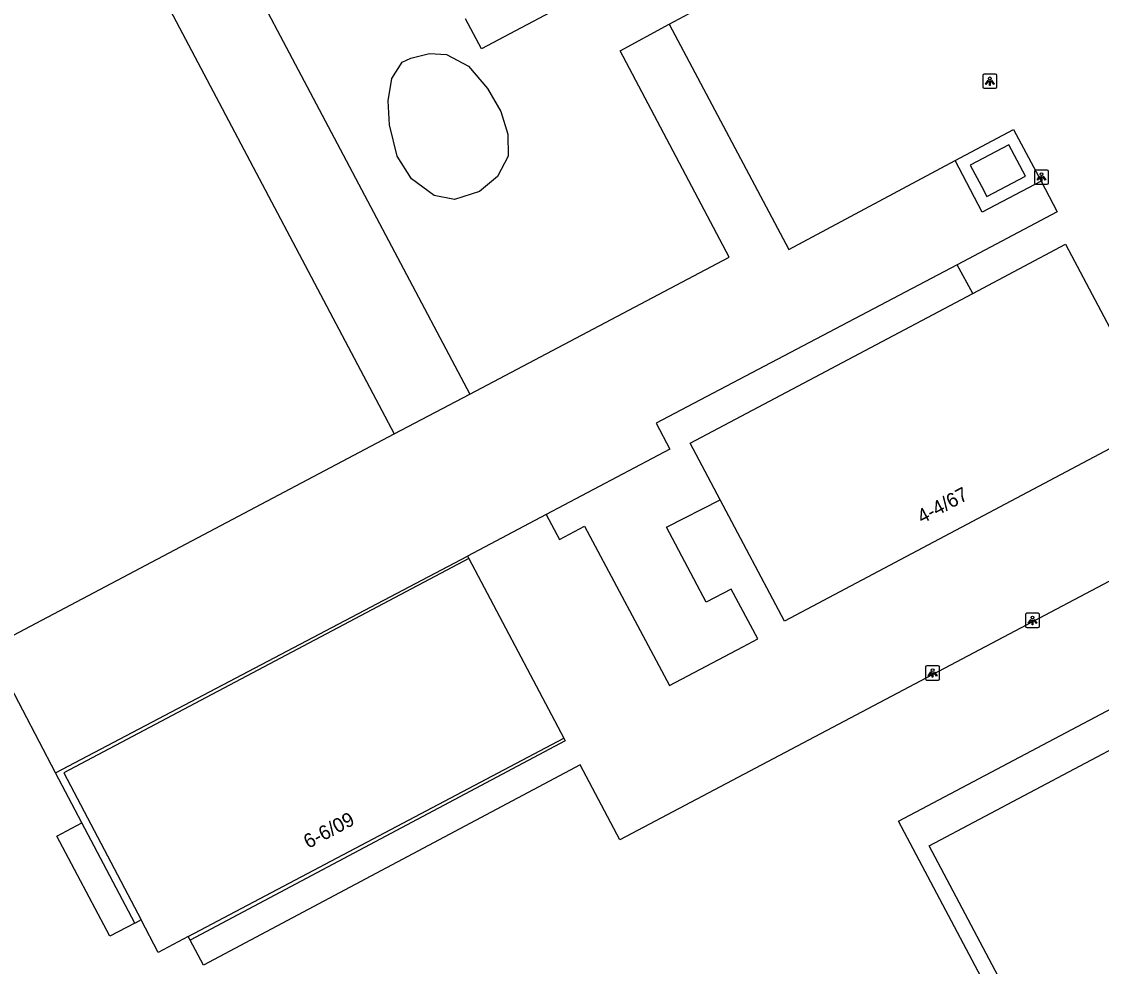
# Model space of a CAD drawing. Extents: x 162880 to 165536, y 384011 to 385179.
# Drawn here: x 162966.8 to 163042.9, y 384118.4 to 384185 of the extents above; entities that cross this region are included whole.
import ezdxf

# ---------------------------------------------------------------- set-up
doc = ezdxf.new("R2010")
doc.units = 0
for name, color, linetype in [('IMGEO_Groenvoorziening', 7, 'Continuous'), ('IMGEO_Lage_trafo', 7, 'Continuous'), ('IMGEO_Lichtpunt', 7, 'Continuous'), ('IMGEO_Pand', 7, 'Continuous'), ('IMGEO_Pand_nummerreeks', 7, 'Continuous'), ('IMGEO_Rijbaan_lokaal_halfverhard', 7, 'Continuous'), ('IMGEO_Rijbaan_lokaal_open', 7, 'Continuous'), ('IMGEO_Voetpad_open', 7, 'Continuous')]:
    doc.layers.add(name, color=color, linetype=linetype)

msp = doc.modelspace()

# ---------------------------------------------------------------- linework, layer by layer
at = {"layer": 'IMGEO_Groenvoorziening'}
for points in [[(163001.081, 384175.522), (163000.317, 384174.095), (162999.056, 384173.032), (162997.296, 384172.468), (162995.868, 384172.767), (162994.275, 384173.929), (162993.246, 384175.522), (162992.714, 384177.747), (162992.615, 384179.44), (162992.88, 384181.001), (162993.611, 384182.163), (162994.208, 384182.428), (162995.536, 384182.76), (162996.732, 384182.694), (162998.292, 384181.864), (162999.62, 384180.303), (163000.55, 384178.677), (163001.048, 384177.083), (163001.081, 384175.522)], [(162971.023, 384128.547), (162969.176, 384132.079)], [(162975.218, 384121.715), (162974.789, 384121.493), (162974.765, 384121.481)], [(162978.67, 384120.283), (162978.532, 384120.544)]]:
    msp.add_lwpolyline(points, dxfattribs=at)
at = {"layer": 'IMGEO_Lage_trafo'}
msp.add_lwpolyline([(163036.365, 384176.336), (163033.643, 384174.897), (163034.423, 384173.408), (163034.8, 384172.687), (163037.541, 384174.132), (163036.365, 384176.336)], dxfattribs=at)
at = {"layer": 'IMGEO_Lichtpunt'}
for p, q in [((163034.52, 384181.214), (163034.52, 384180.407)), ((163034.52, 384181.214), (163034.52, 384180.407)), ((163035.422, 384181.309), (163034.614, 384181.309)), ((163035.422, 384181.309), (163034.614, 384181.309)), ((163035.516, 384180.407), (163035.516, 384181.214)), ((163035.516, 384180.407), (163035.516, 384181.214)), ((163034.614, 384180.313), (163035.422, 384180.313)), ((163034.614, 384180.313), (163035.422, 384180.313)), ((163038.156, 384174.458), (163038.156, 384173.651)), ((163038.156, 384174.458), (163038.156, 384173.651)), ((163039.058, 384174.553), (163038.25, 384174.553)), ((163039.058, 384174.553), (163038.25, 384174.553)), ((163039.152, 384173.651), (163039.152, 384174.458)), ((163039.152, 384173.651), (163039.152, 384174.458)), ((163038.25, 384173.557), (163039.058, 384173.557)), ((163038.25, 384173.557), (163039.058, 384173.557)), ((163037.525, 384143.227), (163037.525, 384142.42)), ((163037.525, 384143.227), (163037.525, 384142.42)), ((163038.427, 384143.322), (163037.619, 384143.322)), ((163038.427, 384143.322), (163037.619, 384143.322)), ((163038.521, 384142.42), (163038.521, 384143.227)), ((163038.521, 384142.42), (163038.521, 384143.227)), ((163037.619, 384142.326), (163038.427, 384142.326)), ((163037.619, 384142.326), (163038.427, 384142.326)), ((163030.487, 384139.522), (163030.487, 384138.715)), ((163030.487, 384139.522), (163030.487, 384138.715)), ((163031.389, 384139.617), (163030.581, 384139.617)), ((163031.389, 384139.617), (163030.581, 384139.617)), ((163031.483, 384138.715), (163031.483, 384139.522)), ((163031.483, 384138.715), (163031.483, 384139.522)), ((163030.581, 384138.621), (163031.389, 384138.621)), ((163030.581, 384138.621), (163031.389, 384138.621))]:
    msp.add_line(p, q, dxfattribs=at)
for points in [[(163034.894, 384180.878), (163034.933, 384180.85), (163034.745, 384180.588), (163034.707, 384180.615), (163034.894, 384180.878)], [(163034.996, 384180.83), (163035.043, 384180.83), (163035.043, 384180.508), (163034.996, 384180.508), (163034.996, 384180.83)], [(163035.106, 384180.85), (163035.144, 384180.877), (163035.331, 384180.615), (163035.292, 384180.587), (163035.106, 384180.85)], [(163038.53, 384174.122), (163038.569, 384174.094), (163038.381, 384173.832), (163038.343, 384173.859), (163038.53, 384174.122)], [(163038.632, 384174.074), (163038.679, 384174.074), (163038.679, 384173.752), (163038.632, 384173.752), (163038.632, 384174.074)], [(163038.742, 384174.094), (163038.78, 384174.121), (163038.967, 384173.859), (163038.928, 384173.831), (163038.742, 384174.094)], [(163037.899, 384142.891), (163037.938, 384142.863), (163037.75, 384142.601), (163037.712, 384142.628), (163037.899, 384142.891)], [(163038.111, 384142.863), (163038.149, 384142.89), (163038.336, 384142.628), (163038.297, 384142.6), (163038.111, 384142.863)], [(163038.001, 384142.843), (163038.048, 384142.843), (163038.048, 384142.521), (163038.001, 384142.521), (163038.001, 384142.843)], [(163030.861, 384139.186), (163030.9, 384139.158), (163030.712, 384138.896), (163030.674, 384138.923), (163030.861, 384139.186)], [(163030.963, 384139.138), (163031.01, 384139.138), (163031.01, 384138.816), (163030.963, 384138.816), (163030.963, 384139.138)], [(163031.073, 384139.158), (163031.111, 384139.185), (163031.298, 384138.923), (163031.259, 384138.895), (163031.073, 384139.158)]]:
    msp.add_lwpolyline(points, dxfattribs=at)
for centre in [(163035.019, 384181.012), (163038.655, 384174.256), (163038.024, 384143.025), (163030.986, 384139.32)]:
    msp.add_circle(centre, 0.0994, dxfattribs=at)
for centre, start, end in [((163034.614, 384181.214), 90, 180), ((163034.614, 384181.214), 90, 180), ((163035.422, 384181.214), 0, 90), ((163035.422, 384181.214), 0, 90), ((163034.614, 384180.407), 180, 270), ((163034.614, 384180.407), 180, 270), ((163035.422, 384180.407), 270, 0), ((163035.422, 384180.407), 270, 360), ((163038.25, 384174.458), 90, 180), ((163038.25, 384174.458), 90, 180), ((163039.058, 384174.458), 0, 90), ((163039.058, 384174.458), 0, 90), ((163038.25, 384173.651), 180, 270), ((163038.25, 384173.651), 180, 270), ((163039.058, 384173.651), 270, 0), ((163039.058, 384173.651), 270, 360), ((163037.619, 384143.227), 90, 180), ((163037.619, 384143.227), 90, 180), ((163038.427, 384143.227), 0, 90), ((163038.427, 384143.227), 0, 90), ((163037.619, 384142.42), 180, 270), ((163037.619, 384142.42), 180, 270), ((163038.427, 384142.42), 270, 0), ((163038.427, 384142.42), 270, 360), ((163030.581, 384139.522), 90, 180), ((163030.581, 384139.522), 90, 180), ((163031.389, 384139.522), 0, 90), ((163031.389, 384139.522), 0, 90), ((163030.581, 384138.715), 180, 270), ((163030.581, 384138.715), 180, 270), ((163031.389, 384138.715), 270, 0), ((163031.389, 384138.715), 270, 360)]:
    msp.add_arc(centre, 0.0946, start, end, dxfattribs=at)
at = {"layer": 'IMGEO_Pand'}
for points in [[(163033.824, 384165.861), (163040.359, 384169.323), (163046.995, 384156.799), (163020.539, 384142.773), (163016.009, 384151.324)], [(163016.009, 384151.324), (163013.9, 384155.305), (163033.824, 384165.861)], [(162998.314, 384147.178), (162969.758, 384132.092), (162975.218, 384121.715)], [(162998.314, 384147.178), (163004.989, 384134.531)], [(162978.532, 384120.544), (163004.989, 384134.531)], [(162978.532, 384120.544), (162976.422, 384119.428), (162975.218, 384121.715)]]:
    msp.add_lwpolyline(points, dxfattribs=at)
at = {"layer": 'IMGEO_Rijbaan_lokaal_halfverhard'}
for points in [[(162976.298, 384200.493), (162998.376, 384158.768)], [(162970.977, 384197.711), (162993.049, 384155.957)]]:
    msp.add_lwpolyline(points, dxfattribs=at)
at = {"layer": 'IMGEO_Rijbaan_lokaal_open'}
for points in [[(163012.433, 384184.826), (163028.279, 384193.317), (163026.131, 384197.372)], [(162998.376, 384158.768), (163016.641, 384168.406), (163008.959, 384182.964), (163012.433, 384184.826)], [(163012.433, 384184.826), (163020.858, 384168.961), (163032.586, 384175.227)], [(163032.586, 384175.227), (163036.694, 384177.404), (163038.642, 384173.779)], [(163038.642, 384173.779), (163034.488, 384171.596), (163032.586, 384175.227)], [(163038.642, 384173.779), (163039.758, 384171.616), (163032.709, 384167.878)], [(163032.709, 384167.878), (163012.797, 384157.407), (163011.5, 384156.725), (163012.472, 384154.889), (163003.755, 384150.29)], [(163033.824, 384165.861), (163032.709, 384167.878)], [(162993.049, 384155.957), (162998.376, 384158.768)], [(162969.176, 384132.079), (162964.552, 384140.92), (162993.049, 384155.957)], [(163003.755, 384150.29), (163004.694, 384148.532), (163006.45, 384149.463), (163012.439, 384138.224), (163017.619, 384140.953), (163018.66, 384141.514), (163016.801, 384145.021), (163015.021, 384144.114), (163012.238, 384149.396), (163016.009, 384151.324)], [(163083.846, 384127.811), (163085.723, 384124.303), (163069.383, 384115.626), (163064.419, 384125.025), (163037.943, 384111.038), (163028.579, 384128.68), (163055.056, 384142.674), (163051.325, 384149.746), (163023.084, 384134.835), (163008.947, 384127.352), (163006.143, 384132.639), (162979.608, 384118.518), (162978.67, 384120.283)], [(163003.755, 384150.29), (162998.219, 384147.358)], [(162969.176, 384132.079), (162998.219, 384147.358)], [(162998.219, 384147.358), (162998.314, 384147.178)], [(163055.571, 384140.093), (163062.549, 384126.9), (163037.712, 384113.762), (163030.742, 384126.945), (163055.571, 384140.093)], [(163004.989, 384134.531), (163005.098, 384134.326), (162978.67, 384120.283)]]:
    msp.add_lwpolyline(points, dxfattribs=at)
at = {"layer": 'IMGEO_Voetpad_open'}
for points in [[(163026.131, 384197.372), (162999.205, 384183.093), (162998.072, 384185.202)], [(162974.765, 384121.481), (162972.998, 384120.566), (162969.284, 384127.625), (162971.023, 384128.547)], [(162974.765, 384121.481), (162971.023, 384128.547)]]:
    msp.add_lwpolyline(points, dxfattribs=at)

# ---------------------------------------------------------------- texts
at = {"layer": 'IMGEO_Pand_nummerreeks'}
for s, rotation, p in [('4-4/67', 27.93169, (163030.237, 384149.612)), ('6-6/09', 27.86294, (162986.994, 384126.715))]:
    msp.add_text(s, height=1, rotation=rotation, dxfattribs=at).set_placement(p)

doc.saveas('drawing.dxf')
